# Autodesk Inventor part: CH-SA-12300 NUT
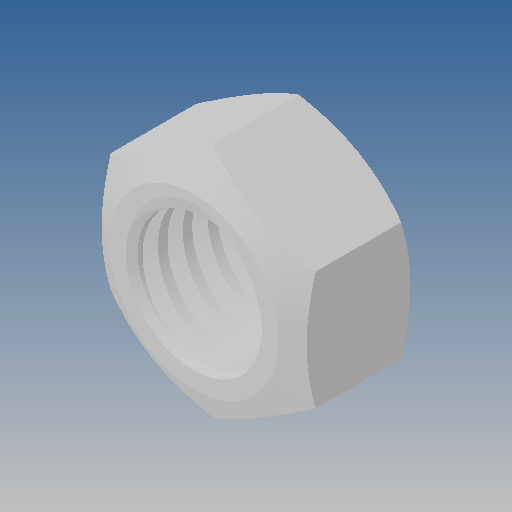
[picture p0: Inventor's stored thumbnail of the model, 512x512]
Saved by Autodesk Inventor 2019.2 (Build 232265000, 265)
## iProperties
Created: 2012-09
Part Number: CH-SA-12300 NUT
Material: Ogólny
Document SubType Name: Modeling
Designer: CADENGINEERING4
Density: 1 g/cm^3
Appearance: Domyślna
Author: CADENGINEERING4
Revision Number: ÈÎºÎ
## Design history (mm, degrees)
feature "ÇÐ³ý-É¨Ãè2"
node "Bryła1"
